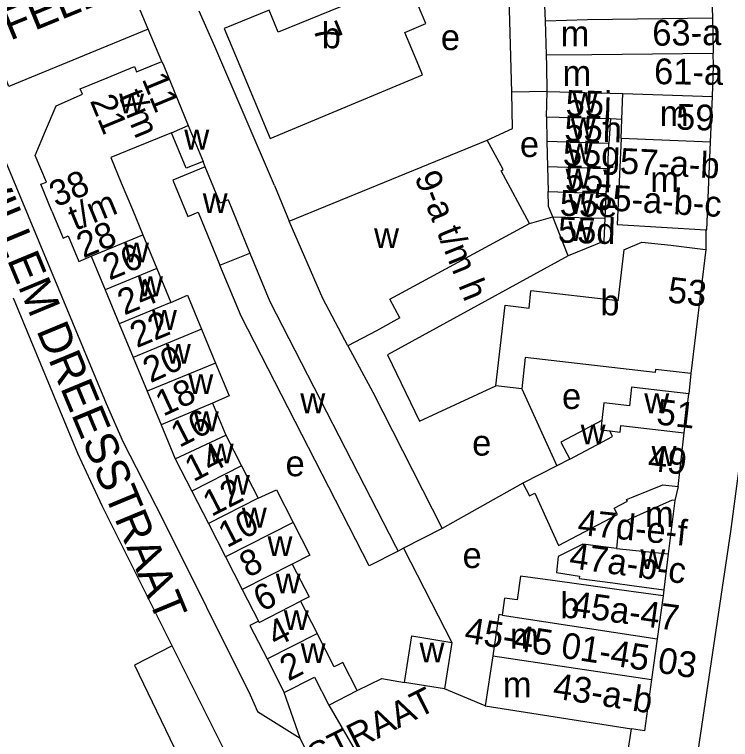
# Model space of a CAD drawing. Extents: x 159902 to 161769, y 383692 to 384875.
# Drawn here: x 161012.9 to 161124, y 384145.4 to 384258 of the extents above; entities that cross this region are included whole.
import ezdxf

# ---------------------------------------------------------------- set-up
doc = ezdxf.new("R2010")
doc.units = 0
for name, color, linetype in [('BLT_Basislijn', 7, 'Continuous'), ('BLT_Bebouwing', 7, 'Continuous'), ('BLT_Centroide', 7, 'Continuous'), ('BLT_Huisnummer', 7, 'Continuous'), ('BLT_Huisnummer_ tussenligend', 7, 'Continuous'), ('BLT_Huisnummer_reeks', 7, 'Continuous'), ('BLT_Onderverdeling_panden', 7, 'Continuous'), ('BLT_Straatnaam', 7, 'Continuous'), ('BLT_Straatnaam_verkleind', 7, 'Continuous'), ('BLT_Vlakafsluiter', 7, 'Continuous')]:
    doc.layers.add(name, color=color, linetype=linetype)

msp = doc.modelspace()

# ---------------------------------------------------------------- linework, layer by layer
at = {"layer": 'BLT_Basislijn'}
for p, q in [((161090.05, 384245.92), (161089.58, 384263.2)), ((161033.65, 384255.7), (161032.4, 384258.67)), ((161035.76, 384250.69), (161033.65, 384255.7)), ((161095.56, 384246.05), (161090.05, 384245.92)), ((161053.21, 384231.45), (161055.52, 384225.89)), ((161092.79, 384225.53), (161096.42, 384226.57)), ((161120.19, 384224.56), (161120.15, 384221.51)), ((161117.86, 384202.24), (161117.52, 384199.1)), ((161091.61, 384199.87), (161097.06, 384187.94)), ((161091.75, 384185.24), (161079.24, 384178.19)), ((161115.87, 384184.71), (161115.38, 384182.55)), ((161073.24, 384175.12), (161072.4, 384174.69)), ((161073.24, 384175.12), (161080.76, 384160.5)), ((161085.92, 384150.63), (161079.63, 384153.28)), ((161057.24, 384145.63), (161054.76, 384152.73)), ((161061.66, 384150.76), (161066.82, 384141.89)), ((161059.19, 384141.51), (161057.24, 384145.63))]:
    msp.add_line(p, q, dxfattribs=at)
for points in [[(161129.51, 384286.96), (161130.75, 384273.62), (161130.85, 384254.44), (161130.21, 384235.22), (161128.68, 384216.03), (161126.54, 384196.86), (161124.02, 384177.72), (161118.2, 384138.73)], [(161053.21, 384231.45), (161043.97, 384253.02), (161041.53, 384258.51)], [(161033.65, 384255.7), (161012.03, 384246.8), (161010.87, 384249.81)], [(161006.17, 384247.88), (161027.11, 384197.59), (161029.77, 384191.59)], [(161086.26, 384238.48), (161090.16, 384240.27), (161090.05, 384245.92)], [(161042.5, 384234.32), (161042.14, 384235.19)], [(161098.79, 384220.53), (161070.79, 384205.15), (161075.74, 384194.84), (161087.59, 384200.33)], [(161037.35, 384159.99), (161026.56, 384181.58), (161024.73, 384185.48), (161022.74, 384189.84), (161012.72, 384213.93)], [(161064.64, 384206.55), (161068.48, 384199.37), (161079.24, 384178.19)], [(161029.77, 384191.59), (161035.83, 384179.7), (161049.47, 384152.35), (161050.6, 384149.77), (161057.24, 384145.63)], [(161079.24, 384178.19), (161073.24, 384175.12)], [(161037.35, 384159.99), (161031.49, 384156.98), (161039.07, 384141.28)], [(161045.2, 384144.26), (161037.35, 384159.99)], [(161066.07, 384153.03), (161069.87, 384154.89), (161073.41, 384154.3)]]:
    msp.add_lwpolyline(points, dxfattribs=at)
at = {"layer": 'BLT_Bebouwing'}
for p, q in [((161120.82, 384269.42), (161121.22, 384257.47)), ((161095.27, 384257.02), (161094.85, 384268.61)), ((161095.43, 384251.72), (161095.27, 384257.02)), ((161121.22, 384257.47), (161121.33, 384251.99)), ((161095.42, 384242.08), (161095.56, 384246.05)), ((161120.89, 384238.17), (161121.18, 384245.28)), ((161095.42, 384242.08), (161095.52, 384238.26)), ((161105.38, 384241.83), (161105.13, 384237.98)), ((161105.38, 384241.83), (161107.14, 384241.76)), ((161107.03, 384238.74), (161107.14, 384241.76)), ((161039.86, 384240.75), (161042.14, 384235.19)), ((161037.24, 384239.64), (161031.75, 384237.38)), ((161055.52, 384225.89), (161086.26, 384238.48)), ((161095.52, 384238.26), (161095.62, 384234.39)), ((161104.94, 384234.08), (161105.13, 384237.98)), ((161031.75, 384237.38), (161027.85, 384235.78)), ((161027.85, 384235.78), (161029.46, 384231.87)), ((161095.62, 384234.39), (161095.72, 384230.53)), ((161104.72, 384230.2), (161104.94, 384234.08)), ((161029.46, 384231.87), (161031.18, 384227.71)), ((161104.54, 384226.35), (161104.73, 384230.21)), ((161046.05, 384229.19), (161049.41, 384220.95)), ((161031.18, 384227.71), (161032.81, 384223.77)), ((161104.4, 384222.82), (161104.54, 384226.35)), ((161120.05, 384224.57), (161120.19, 384224.56)), ((161032.81, 384223.77), (161034.97, 384218.53)), ((161107.42, 384221.45), (161110.22, 384222.65)), ((161120.15, 384221.51), (161117.86, 384202.24)), ((161119.69, 384221.56), (161120.15, 384221.51)), ((161024.8, 384220.46), (161026.97, 384215.22)), ((161034.97, 384218.53), (161037.14, 384213.29)), ((161026.97, 384215.22), (161029.13, 384209.98)), ((161029.13, 384209.98), (161031.3, 384204.74)), ((161041.92, 384209.13), (161044.1, 384203.85)), ((161031.3, 384204.74), (161033.47, 384199.5)), ((161033.47, 384199.5), (161035.63, 384194.26)), ((161116.83, 384193.03), (161117.52, 384199.1)), ((161043.6, 384197.67), (161045.67, 384192.66)), ((161035.63, 384194.26), (161037.8, 384189.02)), ((161045.67, 384192.66), (161048.11, 384187.94)), ((161115.87, 384184.71), (161116.83, 384193.03)), ((161037.8, 384189.02), (161040.39, 384183.98)), ((161048.11, 384187.94), (161050.71, 384182.91)), ((161040.39, 384183.98), (161042.97, 384178.94)), ((161115.38, 384182.55), (161114.34, 384174.27)), ((161042.97, 384178.94), (161045.63, 384173.77)), ((161106.67, 384178.87), (161106.29, 384175.1)), ((161045.63, 384173.77), (161048.23, 384168.69)), ((161114.34, 384174.27), (161113.64, 384168.66)), ((161048.23, 384168.69), (161050.73, 384163.82)), ((161113.53, 384167.74), (161112.61, 384161.06)), ((161113.64, 384168.66), (161113.53, 384167.74)), ((161057.28, 384166.9), (161059.84, 384161.9)), ((161112.61, 384161.06), (161111.74, 384154.72)), ((161080.76, 384160.5), (161079.63, 384153.28)), ((161087.14, 384158.44), (161085.92, 384150.63))]:
    msp.add_line(p, q, dxfattribs=at)
for points in [[(161075.63, 384250), (161073.44, 384255.2), (161076.73, 384256.59), (161072.44, 384266.78), (161065.41, 384263.91), (161066.77, 384260.58), (161053.8, 384255.26), (161052.42, 384258.66), (161045.41, 384255.8), (161047.84, 384250), (161052.54, 384238.75), (161076.2, 384248.64), (161075.63, 384250)], [(161095.56, 384246.05), (161095.48, 384250), (161095.43, 384251.72)], [(161121.18, 384245.28), (161121.38, 384250), (161121.33, 384251.99)], [(161027.29, 384248.18), (161031.5, 384249.92), (161031.84, 384249.07)], [(161031.84, 384249.07), (161034.09, 384250), (161035.76, 384250.69)], [(161035.76, 384250.69), (161036.05, 384250), (161039.86, 384240.75)], [(161023.42, 384245.6), (161023.08, 384246.43), (161027.29, 384248.18)], [(161017.72, 384239.95), (161019.33, 384243.82), (161023.42, 384245.6)], [(161017.86, 384231.98), (161016.11, 384236.08), (161017.72, 384239.95)], [(161042.14, 384235.19), (161039.51, 384234.11), (161037.24, 384239.64)], [(161107.03, 384238.74), (161106.42, 384225.36), (161120.19, 384224.56)], [(161092.79, 384225.53), (161088.4, 384233.74), (161088.74, 384233.92), (161086.26, 384238.48)], [(161120.19, 384224.56), (161120.33, 384224.55), (161120.89, 384238.17)], [(161042.5, 384234.32), (161037.48, 384232.26), (161039.79, 384226.63), (161041.39, 384227.28), (161044.77, 384219.05)], [(161046.05, 384229.19), (161044.82, 384228.69), (161042.5, 384234.32)], [(161018.69, 384227.44), (161016.96, 384231.65), (161017.86, 384231.98)], [(161096.42, 384226.57), (161095.78, 384228.18), (161095.72, 384230.53)], [(161018.69, 384227.44), (161020.42, 384223.24), (161021.24, 384223.61)], [(161098.79, 384220.53), (161096.42, 384226.57)], [(161064.64, 384206.55), (161060.76, 384213.91), (161055.52, 384225.89)], [(161072.66, 384210.88), (161071.11, 384213.77), (161092.79, 384225.53)], [(161021.24, 384223.61), (161022.88, 384219.64), (161024.8, 384220.46)], [(161104.4, 384222.82), (161098.79, 384220.53)], [(161110.22, 384222.65), (161114.73, 384222.15), (161119.69, 384221.56)], [(161049.41, 384220.95), (161052.49, 384213.42), (161072.02, 384175.43), (161072.4, 384174.69)], [(161107.42, 384221.45), (161106.51, 384213.55), (161093.03, 384215.1)], [(161072.4, 384174.69), (161067.95, 384172.4), (161048.04, 384211.13), (161044.77, 384219.05)], [(161087.59, 384200.33), (161089.03, 384212.84), (161092.77, 384212.41), (161093.03, 384215.1)], [(161037.14, 384213.29), (161039.74, 384214.39), (161041.92, 384209.13)], [(161072.66, 384210.88), (161069.07, 384208.88), (161064.64, 384206.55)], [(161044.1, 384203.85), (161046.19, 384198.8), (161043.6, 384197.67)], [(161117.86, 384202.24), (161112.36, 384202.89), (161112.3, 384202.41), (161092.16, 384204.72), (161091.61, 384199.87)], [(161091.61, 384199.87), (161087.59, 384200.33)], [(161117.52, 384199.1), (161112.56, 384199.67), (161108.65, 384200.12), (161108.32, 384197.23), (161104.36, 384197.68), (161104.05, 384194.97)], [(161104.05, 384194.97), (161097.65, 384191.59), (161099.04, 384188.95)], [(161104.05, 384194.97), (161103.88, 384193.48), (161105.25, 384193.33)], [(161099.04, 384188.95), (161097.06, 384187.94)], [(161097.06, 384187.94), (161091.75, 384185.24)], [(161091.75, 384185.24), (161092.8, 384183.25), (161093.64, 384183.69), (161097.29, 384175.52), (161106.44, 384180.35), (161105.93, 384181.33), (161107.99, 384182.42), (161107.84, 384182.7)], [(161107.84, 384182.7), (161108.88, 384183.12), (161113.52, 384184.99), (161115.87, 384184.71)], [(161050.71, 384182.91), (161053.53, 384184.17), (161056.13, 384179.13)], [(161115.38, 384182.55), (161114.94, 384182.61), (161111.04, 384180.85), (161106.67, 384178.87)], [(161056.13, 384179.13), (161058.74, 384174.07), (161056, 384172.66)], [(161106.29, 384175.1), (161101.06, 384175.76), (161097.23, 384173.86), (161096.98, 384171.33), (161100.58, 384170.77), (161100.54, 384170.4), (161105.73, 384169.74), (161108.69, 384169.34), (161113.64, 384168.66)], [(161056, 384172.66), (161058.62, 384167.59), (161057.28, 384166.9)], [(161097.13, 384169.99), (161091.39, 384170.78), (161090.88, 384167.1), (161088.92, 384167.37), (161088.56, 384164.75)], [(161113.53, 384167.74), (161108.57, 384168.42), (161097.13, 384169.99)], [(161088.56, 384164.75), (161088.03, 384164.83), (161087.14, 384158.44)], [(161050.73, 384163.82), (161049.43, 384163.15), (161052.1, 384157.94)], [(161066.07, 384153.03), (161063.84, 384157.38), (161062.51, 384156.69), (161059.84, 384161.9)], [(161073.41, 384154.3), (161074.53, 384161.52), (161080.76, 384160.5)], [(161052.1, 384157.94), (161054.76, 384152.73)], [(161054.76, 384152.73), (161059.42, 384155.11), (161061.66, 384150.76)], [(161079.63, 384153.28), (161073.41, 384154.3)], [(161111.74, 384154.72), (161110.64, 384146.77), (161108.63, 384147.09)], [(161061.66, 384150.76), (161066.07, 384153.03)], [(161085.92, 384150.63), (161108.63, 384147.09)]]:
    msp.add_lwpolyline(points, dxfattribs=at)
at = {"layer": 'BLT_Onderverdeling_panden'}
for p, q in [((161095.27, 384257.02), (161101.81, 384257.21)), ((161101.81, 384257.21), (161121.22, 384257.47)), ((161095.43, 384251.72), (161102.46, 384251.79)), ((161102.46, 384251.79), (161121.33, 384251.99)), ((161095.56, 384246.05), (161107.29, 384245.7)), ((161107.14, 384241.76), (161107.29, 384245.7)), ((161107.29, 384245.7), (161121.18, 384245.28)), ((161095.42, 384242.08), (161105.38, 384241.83)), ((161037.24, 384239.64), (161039.86, 384240.75)), ((161120.89, 384238.17), (161107.03, 384238.74)), ((161105.13, 384237.98), (161095.52, 384238.26)), ((161095.62, 384234.39), (161104.94, 384234.08)), ((161095.72, 384230.53), (161104.72, 384230.2)), ((161096.42, 384226.57), (161104.54, 384226.35)), ((161024.8, 384220.46), (161032.81, 384223.77)), ((161044.77, 384219.05), (161049.41, 384220.95)), ((161034.97, 384218.53), (161026.97, 384215.22)), ((161037.14, 384213.29), (161029.13, 384209.98)), ((161041.92, 384209.13), (161031.3, 384204.74)), ((161044.1, 384203.85), (161033.47, 384199.5)), ((161043.6, 384197.67), (161035.63, 384194.26)), ((161037.8, 384189.02), (161045.67, 384192.66)), ((161105.25, 384193.33), (161106.86, 384193.14)), ((161048.11, 384187.94), (161040.39, 384183.98)), ((161050.71, 384182.91), (161042.97, 384178.94)), ((161056.13, 384179.13), (161045.63, 384173.77)), ((161106.29, 384175.1), (161114.34, 384174.27)), ((161056, 384172.66), (161048.23, 384168.69)), ((161088.56, 384164.75), (161112.61, 384161.06)), ((161052.1, 384157.94), (161059.84, 384161.9)), ((161087.14, 384158.44), (161111.74, 384154.72))]:
    msp.add_line(p, q, dxfattribs=at)
for points in [[(161106.86, 384193.14), (161106.97, 384194.17), (161116.83, 384193.03)], [(161099.04, 384188.95), (161105.7, 384192.46), (161105.25, 384193.33)], [(161050.73, 384163.82), (161050.85, 384163.6), (161057.28, 384166.9)]]:
    msp.add_lwpolyline(points, dxfattribs=at)
at = {"layer": 'BLT_Vlakafsluiter'}
msp.add_line((161107.62, 384140.32), (161108.63, 384147.09), dxfattribs=at)

# ---------------------------------------------------------------- texts
at = {"layer": 'BLT_Centroide'}
for s, p in [('b', (161060.57, 384252.75)), ('e', (161079.05, 384252.46)), ('m', (161097.65, 384253.05)), ('m', (161097.93, 384246.9)), ('w', (161029.12, 384242.62)), ('w', (161099.5, 384242.75)), ('m', (161113.02, 384240.66)), ('w', (161099.22, 384238.82)), ('w', (161039.24, 384237.02)), ('e', (161091.32, 384235.86)), ('w', (161098.71, 384234.89)), ('w', (161098.42, 384230.96)), ('m', (161111.54, 384230.42)), ('w', (161042.1, 384227.16)), ('w', (161098.87, 384227.04)), ('w', (161098.87, 384222.8)), ('w', (161068.69, 384221.71)), ('w', (161029.89, 384219.5)), ('w', (161032.05, 384214.25)), ('b', (161103.79, 384211.28)), ('w', (161034.22, 384209.03)), ('w', (161036.39, 384203.78)), ('w', (161039.87, 384199.06)), ('e', (161097.85, 384196.74)), ('w', (161057.24, 384196.09)), ('w', (161110.62, 384196.09)), ('w', (161040.72, 384193.28)), ('w', (161100.75, 384191.25)), ('e', (161083.91, 384189.5)), ('w', (161043.03, 384188.31)), ('w', (161111.75, 384187.91)), ('e', (161054.95, 384186.3)), ('w', (161045.55, 384183.44)), ('w', (161048.17, 384178.34)), ('m', (161110.74, 384178.44)), ('w', (161052.16, 384173.91)), ('e', (161082.42, 384172.05)), ('w', (161110, 384171.88)), ('w', (161053.43, 384168.12)), ('b', (161097.58, 384164.26)), ('w', (161054.69, 384162.41)), ('m', (161089.79, 384159.54)), ('w', (161057.3, 384157.31)), ('w', (161075.74, 384157.39)), ('m', (161088.66, 384151.96))]:
    msp.add_text(s, height=4, dxfattribs=at).set_placement(p)
at = {"layer": 'BLT_Huisnummer'}
for s, rotation, p in [('7', 292.0859, (161059.09, 384255.87)), ('55j', 358.2982, (161098.37, 384242.27)), ('59', 358.2982, (161115.51, 384240.13)), ('55h', 358.2982, (161098.18, 384238.37)), ('55g', 358.2982, (161097.95, 384234.53)), ('55f', 358.2982, (161098.25, 384230.59)), ('55e', 358.2982, (161097.47, 384226.75)), ('55d', 358.2982, (161097.19, 384222.59)), ('26', 22.4596, (161027.61, 384216.66)), ('53', 353.2201, (161114.12, 384213.32)), ('22', 22.4622, (161031.86, 384206.17)), ('18', 24.8005, (161035.96, 384195.53)), ('51', 353.4525, (161112.38, 384194.37)), ('14', 27.1586, (161040.64, 384185.35)), ('49', 353.4356, (161111.05, 384187.19)), ('10', 27.1594, (161045.85, 384175.12)), ('6', 27.1017, (161051.28, 384165.17)), ('2', 27.1031, (161055.39, 384154.4))]:
    msp.add_text(s, height=4, rotation=rotation, dxfattribs=at).set_placement(p)
at = {"layer": 'BLT_Huisnummer_ tussenligend'}
for s, rotation, p in [('24', 22.4622, (161029.92, 384211.24)), ('20', 24.8005, (161034, 384200.72)), ('16', 27.1586, (161038.47, 384190.67)), ('12', 27.1594, (161043.45, 384179.96)), ('8', 27.1017, (161049.12, 384170.48)), ('4', 27.1031, (161053.45, 384159.7))]:
    msp.add_text(s, height=4, rotation=rotation, dxfattribs=at).set_placement(p)
at = {"layer": 'BLT_Huisnummer_reeks'}
for s, rotation, p in [('63-a', 0.6071, (161111.88, 384253.13)), ('61-a', 359.2945, (161112.12, 384247.18)), ('11', 292.4508, (161032.6, 384247.99)), ('21', 292.3628, (161024.55, 384244.6)), ('t/m', 292.4518, (161028.99, 384245.37)), ('57-a-b', 357.2166, (161106.77, 384233.28)), ('38', 22.4169, (161019.33, 384228.03)), ('9-a t/m h', 292.0859, (161074.9, 384232.76)), ('55-a-b-c', 356.6785, (161102.62, 384227.7)), ('t/m', 22.4154, (161022.3, 384224.37)), ('28', 22.4596, (161023.57, 384220.1)), ('47d-e-f', 354.1028, (161100.16, 384177.22)), ('47a-b-c', 352.16, (161098.84, 384172.06)), ('45a-47', 352.1828, (161099.23, 384164.54)), ('45-45 01-45 03', 351.1414, (161082.56, 384160.5)), ('43-a-b', 351.1414, (161096.29, 384151.85))]:
    msp.add_text(s, height=4, rotation=rotation, dxfattribs=at).set_placement(p)
at = {"layer": 'BLT_Straatnaam'}
for s, rotation, p in [('NIEUWE FELLENOORD', 22.2149, (160985.73, 384243.09)), ('DR WILLEM DREESSTRAAT', 292.5477, (161001.28, 384244.98))]:
    msp.add_text(s, height=5, rotation=rotation, dxfattribs=at).set_placement(p)
at = {"layer": 'BLT_Straatnaam_verkleind'}
msp.add_text('DR WILLEM DREESSTRAAT', height=4, rotation=26.6222, dxfattribs=at).set_placement((161015.27, 384118.46))

doc.saveas('drawing.dxf')
